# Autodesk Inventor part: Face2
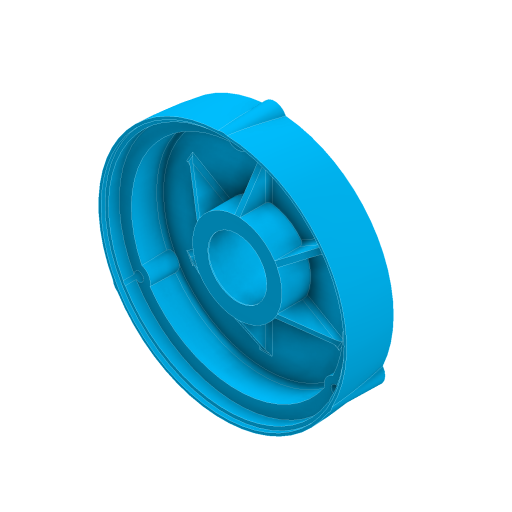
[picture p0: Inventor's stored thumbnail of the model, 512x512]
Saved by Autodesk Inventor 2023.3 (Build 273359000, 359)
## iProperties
Created: 2023-12
Part Number: Face2
Material: Générique
Document SubType Name: Modeling
Designer: Thier
Density: 1 g/cm^3
Appearance: Bleu ciel moyen
Author: Thier
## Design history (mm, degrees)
sketch "Esquisse1"
  geometry: L1 (-66.97, 15.693)-(-61, 15.693); L2 (-61, 15.693)-(-61, -3.307); L3 (-61, -3.307)-(-25.756, -3.307); L4 (-23.3, -15.667)-(-20, -15.667); L5 (-20, -15.667)-(-20, -16.867); L6 (-29.5, -8.307)-(-68.565, -8.307); L7 (-66.97, 21.693)-(-71.5, 21.693); L8 (-29.5, -8.307)-(-29.5, -16.867); L9 (-29.5, -16.867)-(-20, -16.867); L10 (0, 0)-(0, 46.27); L11 (-66.97, 21.693)-(-66.97, 15.693); L12 (-25.756, 15.133)-(-17, 15.133); L13 (-20, 12.633)-(-17, 12.633); L14 (-17, 12.633)-(-17, 15.133); L15 (-20, 12.633)-(-20, -13.867); L16 (-20, -13.867)-(-23.3, -13.867); L17 (-23.3, -13.867)-(-23.3, -15.667); L18 (-25.756, 15.133)-(-25.756, -3.307); A1 r 204.34 centre (132.783, 26.536) between (-71.5, 21.693) and (-68.565, -8.307); 7 further points
  constraints: 36 end point, 7 perpendicular, 5 midpoint, 5 vertical, 3 horizontal, 2 point on circle, 1 centre point, 1 parallel, 1 point on line
  dimensions: "d0" = 408.68 diameter of A1; "d5" = 30 distance between parallel lines of L7 L6; "d13" = 143 diameter of L7.end L10; "d15" = 133.94 diameter of point (-66.97, 18.693) L10; "d16" = 122 diameter of L2 L10; "d20" = 34 diameter of L14 L10; "d23" = 32 distance between parallel lines of L9 L12; "d24" = 6.56 distance between parallel lines of L7 L12; "d26" = 51.51161 diameter of L12.start L10 (derived); "d27" = 2.5 distance between parallel lines of L13 L12; "d29" = 6 distance of L7.start L1.start; "d30" = 5 distance between parallel lines of L6 L3; "d31" = 1.8 distance of L4.start L16.end; "d32" = 40 diameter of L15 L10; "d33" = 40 diameter of point (-20, -16.267) L10; "d82" = 46.6 diameter of point (-23.3, -14.767) L10; "d83" = 59 diameter of L8 L10; "d84" = 3 distance from line of L9 point (-21.65, -13.867)
revolve "Révolution1" sketch "Esquisse1" stored, may be unused: angle "d34" = 90 deg
sketch "Esquisse2"
  geometry: L1 (24.417, 14.149)-(50.123, -3.307); L2 (61, -3.307)-(-61, -3.307) reference; L3 (50.123, -3.307)-(24.417, -3.307); L4 (25.756, -3.307)-(-25.756, -3.307) reference; L5 (24.417, 14.149)-(24.417, -3.307); 1 further point
  constraints: 6 end point, 2 point on line, 1 vertical
  dimensions: "d36" = 50.12269 horizontal distance of point (0, 0) L1.end
extrude "Extrusion1" join sketch "Esquisse2" stored distance "d38" = 3; taper "d39" = 0 deg
fillet "Congé1" dims "d40" = 2
pattern_circular "Réseau circulaire1" dims angle "d42" = 360 deg
fillet "Congé3" dims "d45" = 2
fillet "Congé4" dims "d46" = 2
fillet "Congé5" dims "d47" = 5
sketch "Esquisse4"
  geometry: C1 r 6.5 at (0, 65.49); C2 r 71.5 at (0, 0) reference; 1 further point
  constraints: 1 centre point
  dimensions: "d56" = 65.49 distance of C2.centre C1.centre; "d57" = 0 horizontal distance of C2.centre C1.centre; "d58" = 13 diameter of C1
extrude "Extrusion2" join sketch "Esquisse4" stored distance "d59" = 10; taper "d60" = 1 deg
sketch "Esquisse5"
  geometry: A1 r 68.565 centre (0, 0) between (-6.454, 68.26) and (6.454, 68.26) reference; 2 further points
  dimensions: "d68" = 0 horizontal distance of A1.centre point (0, 65.49); "d69" = 65.49 distance of A1.centre point (0, 65.49)
hole "Perçage2" sketch "Esquisse5" at (0, 65.49) diameter "d61" = 5.5; stored, may be unused: countersink angle "d65" = 90 deg, drill point angle "d67" = 118 deg; dims "d62" = 6, "d63" = 10, "d64" = 10, "d66" = 8
pattern_circular "Réseau circulaire2" dims angle "d71" = 360 deg
sketch "Esquisse7"
  geometry: C1 r 68 at (0, -65.49); 1 further point
  constraints: 1 centre point, 1 coincident
  dimensions: "d76" = 136 diameter of C1
extrude "Extrusion4" cut sketch "Esquisse7" distance "d77" = 8.5; taper "d78" = 0 deg
sketch "Esquisse8"
  geometry: C1 r 70 at (0, -65.49); 1 further point
  constraints: 1 centre point, 1 coincident
  dimensions: "d79" = 140 diameter of C1
extrude "Extrusion5" cut sketch "Esquisse8" distance "d80" = 2.3; taper "d81" = 0 deg
node "Solide1"
